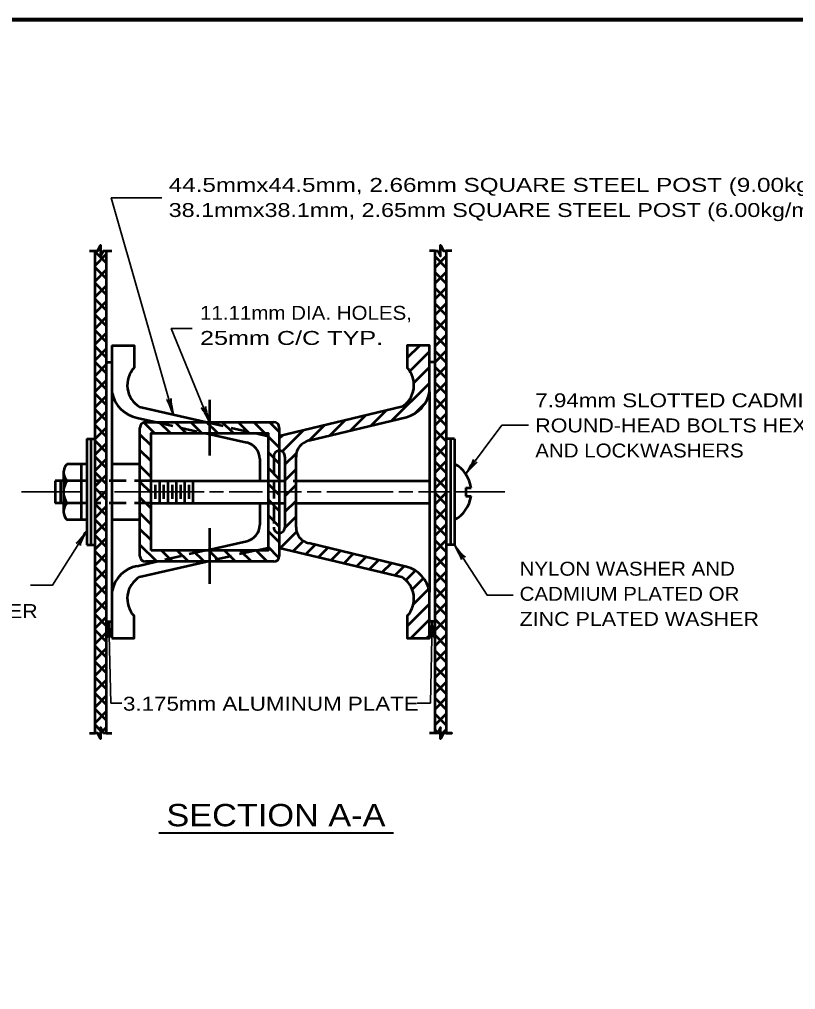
# Model space of a CAD drawing. Extents: x -96 to 759, y -450 to 94.
# Drawn here: x 364.6 to 531.7, y -120.9 to 87.9 of the extents above; entities that cross this region are included whole.
import ezdxf
from ezdxf.enums import TextEntityAlignment as Align

# ---------------------------------------------------------------- set-up
doc = ezdxf.new("R2010")
doc.units = 0
doc.header["$LTSCALE"] = 1.2
doc.linetypes.add('MEDIUM_DASHED', pattern=[4.5, 3, -1.5])
doc.layers.add('1', color=7, linetype='Continuous', lineweight=53)

msp = doc.modelspace()

# ---------------------------------------------------------------- linework, layer by layer
at = {"layer": '1'}
for p, q in [((379.727, 38.132), (380.927, 38.132)), ((383.327, 35.51), (380.927, 37.91)), ((383.327, 38.132), (384.527, 38.132)), ((454.127, 38.132), (452.927, 38.132)), ((454.127, 37.927), (454.331, 38.132)), ((455.327, 39.127), (455.395, 39.195)), ((455.61, 38.766), (455.327, 39.049)), ((456.527, 37.849), (456.245, 38.132)), ((457.727, 38.132), (456.527, 38.132)), ((380.927, 34.974), (383.327, 37.373)), ((454.127, 34.533), (456.527, 36.933)), ((456.527, 34.455), (454.127, 36.855)), ((383.327, 32.116), (380.927, 34.516)), ((380.927, 31.579), (383.327, 33.979)), ((454.127, 31.139), (456.527, 33.539)), ((456.527, 31.061), (454.127, 33.461)), ((383.327, 28.722), (380.927, 31.122)), ((380.927, 28.185), (383.327, 30.585)), ((454.127, 27.745), (456.527, 30.145)), ((456.527, 27.666), (454.127, 30.066)), ((383.327, 25.328), (380.927, 27.728)), ((380.927, 24.791), (383.327, 27.191)), ((454.127, 24.351), (456.527, 26.751)), ((456.527, 24.272), (454.127, 26.672)), ((383.327, 21.934), (380.927, 24.334)), ((380.927, 21.397), (383.327, 23.797)), ((454.127, 20.957), (456.527, 23.357)), ((456.527, 20.878), (454.127, 23.278)), ((383.327, 18.54), (380.927, 20.94)), ((380.927, 18.003), (383.327, 20.403)), ((454.127, 17.563), (456.527, 19.963)), ((456.527, 17.484), (454.127, 19.884)), ((383.327, 15.146), (380.927, 17.546)), ((380.927, 14.609), (383.327, 17.009)), ((384.527, 17.732), (384.527, -45.269)), ((448.127, 15.04), (450.819, 17.732)), ((448.684, 12.203), (452.927, 16.445)), ((454.127, 14.169), (456.527, 16.569)), ((456.527, 14.09), (454.127, 16.49)), ((383.327, 11.752), (380.927, 14.152)), ((380.927, 11.215), (383.327, 13.615)), ((383.327, 14.132), (384.527, 14.132)), ((449.538, 9.662), (452.927, 13.051)), ((454.127, 14.132), (452.927, 14.132)), ((454.127, 10.774), (456.527, 13.175)), ((456.527, 10.696), (454.127, 13.096)), ((383.327, 8.357), (380.927, 10.757)), ((380.927, 7.821), (383.327, 10.221)), ((444.834, 1.564), (452.927, 9.657)), ((454.127, 7.38), (456.527, 9.78)), ((456.527, 7.302), (454.127, 9.702)), ((383.327, 4.963), (380.927, 7.363)), ((380.927, 4.426), (383.327, 6.827)), ((452.927, 7.773), (452.927, -35.31)), ((454.127, 3.986), (456.527, 6.386)), ((456.527, 3.908), (454.127, 6.308)), ((390.527, 4.532), (404.996, 1.243)), ((405.595, 6.043), (405.595, -5.957)), ((449.812, 3.147), (451.934, 5.27)), ((383.327, 1.569), (380.927, 3.969)), ((380.927, 1.032), (383.327, 3.432)), ((389.995, 2.191), (394.166, 1.243)), ((426.959, -2.704), (448.007, 2.322)), ((435.916, -0.565), (439.158, 2.676)), ((440.375, 0.499), (443.617, 3.741)), ((454.127, 0.592), (456.527, 2.992)), ((456.527, 0.514), (454.127, 2.913)), ((383.327, -1.825), (380.927, 0.575)), ((380.927, -2.362), (383.327, 0.038)), ((390.595, -27.58), (390.595, 0.043)), ((393.754, -1.157), (391.423, 1.174)), ((391.795, 1.243), (419.395, 1.243)), ((397.148, -1.157), (394.748, 1.243)), ((400.542, -1.157), (398.142, 1.243)), ((403.936, -1.157), (401.536, 1.243)), ((407.33, -1.157), (404.93, 1.243)), ((410.725, -1.157), (408.325, 1.243)), ((414.119, -1.157), (411.719, 1.243)), ((417.513, -1.157), (415.113, 1.243)), ((420.595, -0.845), (418.507, 1.243)), ((420.595, 0.043), (420.595, -1.757)), ((426.999, -2.695), (430.24, 0.546)), ((431.458, -1.63), (434.699, 1.611)), ((392.995, -3.792), (390.595, -1.392)), ((404.726, -1.157), (413.593, -3.172)), ((415.555, -1.157), (418.195, -1.757)), ((420.595, -4.239), (418.195, -1.839)), ((420.595, -2.31), (421.322, -1.583)), ((421.201, -5.098), (425.781, -0.518)), ((454.127, -2.802), (456.527, -0.402)), ((456.527, -2.881), (454.127, -0.481)), ((379.127, -2.369), (379.127, -25.169)), ((379.127, -2.369), (380.927, -2.369)), ((380.027, -2.369), (380.027, -25.169)), ((383.327, -5.219), (380.927, -2.819)), ((380.927, -5.756), (383.327, -3.356)), ((454.127, -6.196), (456.527, -3.796)), ((456.527, -6.275), (454.127, -3.875)), ((458.327, -2.369), (456.527, -2.369)), ((457.427, -2.369), (457.427, -25.169)), ((458.327, -2.369), (458.327, -25.169)), ((383.327, -8.613), (380.927, -6.213)), ((392.995, -7.186), (390.595, -4.786)), ((420.595, -7.634), (418.195, -5.234)), ((420.595, -4.907), (420.595, -22.63)), ((421.795, -7.898), (424.288, -5.405)), ((421.795, -6.206), (421.795, -21.331)), ((424.195, -21.331), (424.195, -6.206)), ((379.127, -7.769), (374.927, -7.769)), ((377.927, -7.769), (377.927, -19.768)), ((380.927, -9.15), (383.327, -6.75)), ((390.595, -7.769), (384.527, -7.769)), ((392.995, -10.581), (390.595, -8.181)), ((416.395, -6.682), (416.395, -11.369)), ((454.127, -9.59), (456.527, -7.19)), ((456.527, -9.669), (454.127, -7.269)), ((374.12, -9.575), (374.12, -17.962)), ((383.327, -12.007), (380.927, -9.607)), ((380.927, -12.544), (383.327, -10.144)), ((420.595, -11.028), (418.195, -8.628)), ((421.795, -11.292), (424.195, -8.892)), ((379.127, -11.369), (372.32, -11.369)), ((372.32, -11.369), (372.32, -16.169)), ((373.52, -11.369), (373.52, -16.169)), ((392.995, -13.975), (390.595, -11.575)), ((392.995, -11.369), (418.195, -11.369)), ((393.895, -12.269), (393.895, -15.269)), ((394.795, -11.369), (394.795, -16.169)), ((395.695, -12.269), (395.695, -15.269)), ((396.595, -11.369), (396.595, -16.169)), ((397.495, -12.269), (397.495, -15.269)), ((398.395, -11.369), (398.395, -16.169)), ((399.295, -12.269), (399.295, -15.269)), ((400.195, -11.369), (400.195, -16.169)), ((401.095, -12.269), (401.095, -15.269)), ((401.995, -11.369), (401.995, -16.169)), ((420.595, -14.422), (418.195, -12.022)), ((421.795, -14.686), (424.195, -12.286)), ((424.195, -11.369), (452.927, -11.369)), ((454.127, -12.984), (456.527, -10.584)), ((456.527, -13.063), (454.127, -10.663)), ((383.327, -15.401), (380.927, -13.001)), ((380.927, -15.938), (383.327, -13.538)), ((454.127, -16.378), (456.527, -13.978)), ((456.527, -16.457), (454.127, -14.057)), ((460.727, -12.869), (460.727, -14.668)), ((460.727, -12.869), (461.868, -12.869)), ((379.127, -16.169), (372.32, -16.169)), ((383.327, -18.796), (380.927, -16.396)), ((392.995, -17.369), (390.595, -14.969)), ((392.995, -16.169), (418.195, -16.169)), ((416.395, -16.169), (416.395, -20.855)), ((420.595, -17.816), (418.195, -15.416)), ((421.795, -18.081), (424.195, -15.681)), ((424.195, -16.169), (452.927, -16.169)), ((460.727, -14.668), (461.868, -14.668)), ((380.927, -19.332), (383.327, -16.932)), ((392.995, -20.763), (390.595, -18.363)), ((454.127, -19.773), (456.527, -17.373)), ((456.527, -19.851), (454.127, -17.451)), ((379.127, -19.768), (374.927, -19.768)), ((383.327, -22.19), (380.927, -19.79)), ((380.927, -22.726), (383.327, -20.326)), ((390.595, -19.768), (384.527, -19.768)), ((420.595, -21.21), (418.195, -18.81)), ((421.774, -21.496), (424.195, -19.075)), ((454.127, -23.167), (456.527, -20.767)), ((456.527, -23.245), (454.127, -20.845)), ((392.995, -24.157), (390.595, -21.757)), ((405.595, -21.58), (405.595, -33.58)), ((420.595, -24.604), (418.195, -22.204)), ((420.595, -22.675), (420.641, -22.629)), ((420.828, -25.836), (424.355, -22.309)), ((383.327, -25.584), (380.927, -23.184)), ((380.927, -26.121), (383.327, -23.721)), ((404.726, -26.38), (413.593, -24.365)), ((423.568, -26.49), (425.776, -24.283)), ((448.007, -29.859), (426.959, -24.832)), ((454.127, -26.561), (456.527, -24.161)), ((456.527, -26.639), (454.127, -24.239)), ((379.127, -25.169), (380.927, -25.169)), ((383.327, -28.978), (380.927, -26.578)), ((380.927, -29.515), (383.327, -27.115)), ((394.225, -28.78), (390.595, -25.151)), ((397.619, -28.78), (395.219, -26.38)), ((401.013, -28.78), (398.613, -26.38)), ((404.407, -28.78), (402.007, -26.38)), ((407.801, -28.78), (405.401, -26.38)), ((411.195, -28.78), (408.795, -26.38)), ((414.589, -28.78), (412.189, -26.38)), ((415.555, -26.38), (418.195, -25.78)), ((417.983, -28.78), (415.583, -26.38)), ((420.525, -27.928), (418.195, -25.598)), ((420.595, -25.78), (420.595, -27.58)), ((426.308, -27.145), (428.3, -25.153)), ((429.048, -27.799), (431.04, -25.807)), ((431.788, -28.453), (433.779, -26.461)), ((434.527, -29.107), (436.519, -27.116)), ((458.327, -25.169), (456.527, -25.169)), ((389.995, -29.728), (394.166, -28.78)), ((390.527, -32.069), (404.995, -28.78)), ((419.395, -28.78), (391.795, -28.78)), ((437.267, -29.762), (439.259, -27.77)), ((440.007, -30.416), (441.999, -28.424)), ((442.747, -31.07), (444.739, -29.078)), ((454.127, -29.955), (456.527, -27.555)), ((456.527, -30.034), (454.127, -27.634)), ((383.327, -32.372), (380.927, -29.972)), ((380.927, -32.909), (383.327, -30.509)), ((445.487, -31.725), (447.478, -29.733)), ((447.838, -32.768), (449.887, -30.718)), ((454.127, -33.349), (456.527, -30.949)), ((456.527, -33.428), (454.127, -31.028)), ((383.327, -35.766), (380.927, -33.366)), ((449.195, -34.805), (451.637, -32.363)), ((380.927, -36.303), (383.327, -33.903)), ((449.423, -37.971), (452.752, -34.641)), ((454.127, -36.743), (456.527, -34.343)), ((456.527, -36.822), (454.127, -34.422)), ((383.327, -39.16), (380.927, -36.76)), ((380.927, -39.697), (383.327, -37.297)), ((448.127, -42.66), (452.927, -37.86)), ((454.127, -40.137), (456.527, -37.737)), ((456.527, -40.216), (454.127, -37.816)), ((383.327, -42.554), (380.927, -40.154)), ((380.927, -43.091), (383.327, -40.691)), ((383.327, -41.669), (384.527, -41.669)), ((448.913, -45.269), (452.927, -41.254)), ((454.127, -41.669), (452.927, -41.669)), ((454.127, -43.531), (456.527, -41.131)), ((456.527, -43.61), (454.127, -41.21)), ((383.327, -45.948), (380.927, -43.548)), ((380.927, -46.485), (383.327, -44.085)), ((452.307, -45.269), (452.927, -44.649)), ((454.127, -46.925), (456.527, -44.525)), ((456.527, -47.004), (454.127, -44.604)), ((383.327, -49.343), (380.927, -46.943)), ((380.927, -49.879), (383.327, -47.479)), ((454.127, -50.32), (456.527, -47.919)), ((456.527, -50.398), (454.127, -47.998)), ((383.327, -52.737), (380.927, -50.337)), ((380.927, -53.274), (383.327, -50.873)), ((454.127, -53.714), (456.527, -51.314)), ((456.527, -53.792), (454.127, -51.392)), ((383.327, -56.131), (380.927, -53.731)), ((380.927, -56.668), (383.327, -54.268)), ((454.127, -57.108), (456.527, -54.708)), ((456.527, -57.186), (454.127, -54.786)), ((383.327, -59.525), (380.927, -57.125)), ((380.927, -60.062), (383.327, -57.662)), ((454.127, -60.502), (456.527, -58.102)), ((456.527, -60.581), (454.127, -58.181)), ((383.327, -62.919), (380.927, -60.519)), ((380.927, -63.456), (383.327, -61.056)), ((454.127, -63.896), (456.527, -61.496)), ((456.527, -63.975), (454.127, -61.575)), ((382.127, -65.113), (380.927, -63.913)), ((382.521, -65.256), (383.327, -64.45)), ((379.727, -65.669), (380.927, -65.669)), ((381.721, -66.056), (382.127, -65.65)), ((383.327, -65.669), (384.527, -65.669)), ((454.127, -65.669), (452.927, -65.669)), ((454.827, -65.669), (454.127, -64.969)), ((455.749, -65.669), (456.527, -64.89))]:
    msp.add_line(p, q, dxfattribs=at)
at = {"layer": '1', "linetype": 'MEDIUM_DASHED'}
for p, q in [((394.166, 1.243), (404.726, -1.157)), ((404.996, 1.243), (415.555, -1.157)), ((419.395, -6.206), (419.395, -21.331)), ((392.995, -11.369), (380.927, -11.369)), ((418.195, -11.369), (424.195, -11.369)), ((392.995, -16.169), (380.927, -16.169)), ((418.195, -16.169), (424.195, -16.169)), ((404.726, -26.38), (394.166, -28.78)), ((415.555, -26.38), (404.995, -28.78))]:
    msp.add_line(p, q, dxfattribs=at)
at = {"layer": '1', "lineweight": 35}
for p, q in [((365.12, -13.769), (377.927, -13.769)), ((381.527, -13.769), (382.727, -13.769)), ((385.127, -13.769), (404.395, -13.769)), ((405.595, -13.769), (408.595, -13.769)), ((409.795, -13.769), (416.995, -13.769)), ((418.195, -13.769), (425.395, -13.769)), ((426.595, -13.769), (429.595, -13.769)), ((430.795, -13.769), (445.127, -13.769)), ((449.327, -13.769), (446.327, -13.769)), ((450.527, -13.769), (457.427, -13.769)), ((458.327, -13.769), (469.127, -13.769)), ((383.927, -41.669), (384.317, -59.241)), ((453.527, -41.669), (453.138, -59.241)), ((384.317, -59.241), (386.725, -59.241)), ((450.29, -59.241), (453.138, -59.241))]:
    msp.add_line(p, q, dxfattribs=at)
at = {"layer": '1', "lineweight": 40}
msp.add_line((394.691, -87.119), (445.172, -87.119), dxfattribs=at)
at = {"layer": '1', "lineweight": 158}
msp.add_lwpolyline([(752.818, 87.895), (-38.882, 87.795), (-38.782, -438.205)], dxfattribs=at)
at = {"layer": '1', "lineweight": 35}
for points in [[(397.762, 2.887), (384.422, 49.468), (395.3, 49.468)], [(405.595, 1.243), (397.315, 21.356), (401.827, 21.356)], [(460.713, -9.891), (468.534, 0.565), (474.234, 0.565)], [(379.127, -22.127), (371.788, -33.806), (367.038, -33.806)], [(458.327, -25.169), (465.367, -36.024), (470.909, -36.024)]]:
    msp.add_lwpolyline(points, dxfattribs=at)
at = {"layer": '1'}
for points in [[(380.927, -65.669), (380.927, 38.132), (381.527, 38.132), (382.127, 39.331), (382.127, 36.931), (382.727, 38.132), (383.327, 38.132), (383.327, -65.669), (382.727, -65.669), (382.127, -64.469), (382.127, -66.868), (381.527, -65.669)], [(454.127, -65.669), (454.127, 38.132), (454.727, 38.132), (455.327, 36.931), (455.327, 39.331), (455.927, 38.132), (456.527, 38.132), (456.527, -65.669), (457.727, -65.669)], [(454.127, -65.669), (454.127, 38.132), (454.727, 38.132), (455.327, 36.931), (455.327, 39.331), (455.927, 38.132), (456.527, 38.132), (456.527, -65.669), (455.927, -65.669), (455.327, -66.868), (455.327, -64.469), (454.727, -65.669)], [(392.995, -26.38), (392.995, -1.157), (418.195, -1.157), (418.195, -26.38)]]:
    msp.add_lwpolyline(points, close=True, dxfattribs=at)
for points in [[(384.527, 17.732), (389.327, 17.732), (389.327, 12.931)], [(452.927, 7.773), (452.927, 17.732), (448.127, 17.732), (448.127, 12.931)], [(446.927, 4.532), (420.595, -1.757), (420.595, -4.907)], [(420.595, -22.63), (420.595, -25.78), (446.927, -32.069)], [(448.127, -40.468), (448.127, -45.269), (452.927, -45.269), (452.927, -35.31)], [(384.527, -45.269), (389.327, -45.269), (389.327, -40.468)]]:
    msp.add_lwpolyline(points, dxfattribs=at)
for centre, radius, start, end in [((393.343, 9.219), 5.468, 137.24693, 239.01328), ((444.112, 9.219), 5.468, 300.98672, 42.75307), ((391.321, 8.959), 6.896, 192.24961, 258.91782), ((446.134, 8.959), 6.896, 285.76159, 350.09896), ((391.795, 0.043), 1.2, 90, 180), ((419.395, 0.043), 1.2, 0, 90), ((412.795, -6.682), 3.6, 0, 77.19552), ((427.795, -6.206), 3.6, 103.43049, 180), ((420.585, -6.12), 1.213, 355.93658, 88.42125), ((376.53, -9.569), 2.41, 131.68177, 180.15453), ((455.127, -13.769), 6.8, 7.60558, 61.92751), ((376.53, -9.582), 2.41, 179.84547, 228.31823), ((376.53, -9.569), 2.41, 180.15453, 228.31823), ((378.091, -13.768), 3.971, 142.81241, 217.18759), ((378.091, -13.769), 3.971, 142.81241, 217.18759), ((376.53, -17.956), 2.41, 131.68177, 180.15453), ((376.53, -17.969), 2.41, 131.68177, 179.84548), ((455.127, -13.769), 6.8, 298.07249, 352.39442), ((376.53, -17.969), 2.41, 179.84547, 228.31823), ((412.795, -20.855), 3.6, 282.80434, 0), ((420.585, -21.417), 1.213, 271.57875, 4.06342), ((427.795, -21.331), 3.6, 180, 256.56931), ((391.795, -27.58), 1.2, 180, 270), ((419.395, -27.58), 1.2, 270, 0), ((391.321, -36.496), 6.896, 101.08218, 167.75039), ((446.134, -36.496), 6.896, 9.90104, 74.23791), ((393.343, -36.756), 5.468, 120.98672, 222.75307), ((444.112, -36.756), 5.468, 317.24693, 59.01328)]:
    msp.add_arc(centre, radius, start, end, dxfattribs=at)
at = {"layer": '1', "linetype": 'MEDIUM_DASHED'}
for centre, start, end in [((420.606, -6.12), 91.57875, 184.06342), ((420.606, -21.417), 175.93658, 268.42125)]:
    msp.add_arc(centre, 1.213, start, end, dxfattribs=at)
at = {"layer": '1', "lineweight": 40}
for centre, major_axis, ratio, start_param, end_param in [((397.635, 4.25), (0.378, -2.084), 0.07063, 3.1407148, 5.41811), ((397.082, 4.055), (0.77, -2.008), 0.122415, 0.8963533, 3.1415927), ((404.79, 2.328), (0.989, -1.91), 0.122415, 0.8963533, 3.1415927), ((405.318, 2.583), (0.608, -2.029), 0.07063, 3.1407148, 5.41811), ((461.232, -8.644), (-1.133, -1.828), 0.122415, 0.8963533, 3.1415927), ((461.232, -8.644), (-1.133, -1.828), 0.122415, 0.8963533, 3.1415927), ((461.722, -8.966), (-1.431, -1.562), 0.07063, 3.1407148, 5.41811), ((461.722, -8.966), (-1.431, -1.562), 0.07063, 3.1407148, 5.41811), ((378.197, -23.131), (1.3, 1.673), 0.07063, 3.1407148, 5.41811), ((378.711, -23.412), (0.981, 1.914), 0.122415, 0.8963533, 3.1415927), ((458.846, -26.435), (-0.97, 1.883), 0.07063, 3.1407148, 5.41811), ((459.318, -26.087), (-1.323, 1.696), 0.122415, 0.8963533, 3.1415927), ((383.703, -43.018), (0.164, 2.112), 0.07063, 3.1407148, 5.41811), ((384.288, -42.97), (-0.235, 2.138), 0.122415, 0.8963533, 3.1415927), ((453.244, -43.007), (0.257, 2.103), 0.07063, 3.1407148, 5.41811), ((453.83, -42.985), (-0.14, 2.146), 0.122415, 0.8963533, 3.1415927)]:
    msp.add_ellipse(centre, major_axis=major_axis, ratio=ratio, start_param=start_param, end_param=end_param, dxfattribs=at)

# ---------------------------------------------------------------- texts
at = {"layer": '1'}
for s, width, p in [('44.5mmx44.5mm, 2.66mm SQUARE STEEL POST (9.00kg/m POST)', 1.3, (396.791, 50.779)), ('38.1mmx38.1mm, 2.65mm SQUARE STEEL POST (6.00kg/m POST)', 1.25, (396.791, 45.379)), ('11.11mm DIA. HOLES,', 1.1, (403.53, 23.253)), ('25mm C/C TYP.', 1.35, (403.53, 17.853)), ('7.94mm SLOTTED CADMIUM PLATED', 1.2, (475.694, 4.433)), ('ROUND-HEAD BOLTS HEX. NUTS', 1.15, (475.694, -0.967)), ('AND LOCKWASHERS', 1.1, (475.694, -6.367)), ('NYLON WASHER AND', 1.1, (472.324, -31.801)), ('CADMIUM PLATED OR', 1.1, (472.324, -37.201)), ('ZINC PLATED WASHER', 1.15, (317.046, -40.915)), ('ZINC PLATED WASHER', 1.15, (472.324, -42.601))]:
    msp.add_text(s, height=3, dxfattribs=dict(at, width=width)).set_placement(p)
for s, height, width, p in [('3.175mm ALUMINUM PLATE', 3, 1.2, (418.775, -60.847)), ('SECTION A-A', 4.8, 1.15, (419.869, -85.716))]:
    msp.add_text(s, height=height, dxfattribs=dict(at, width=width)).set_placement(p, align=Align.CENTER)

doc.saveas('drawing.dxf')
